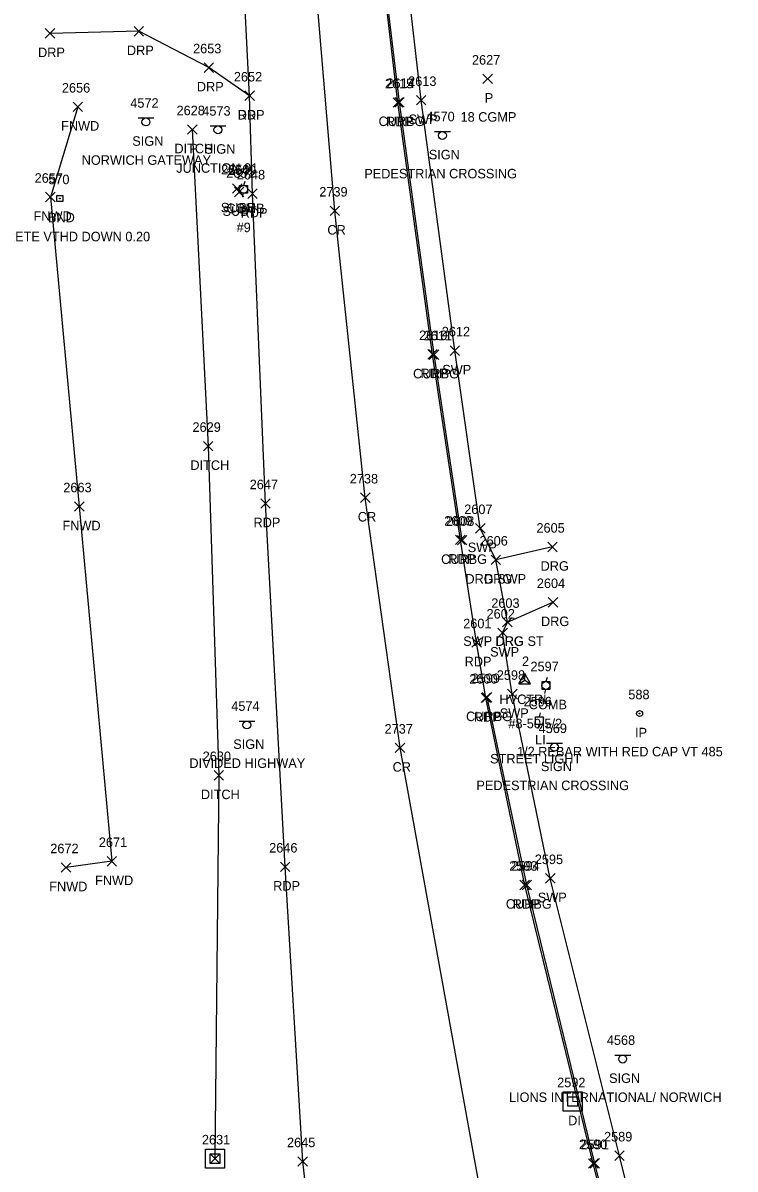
# Model space of a CAD drawing. Extents: x 1690689 to 1696275, y 438760 to 444007.
# Drawn here: x 1691174.2 to 1691323.9, y 441126.4 to 441367.3 of the extents above; entities that cross this region are included whole.
import ezdxf

# ---------------------------------------------------------------- set-up
doc = ezdxf.new("R2010")
doc.units = 0
for name, color, linetype in [('C_A', 7, 'Continuous'), ('C_I', 7, 'Continuous'), ('CPSM', 7, 'Continuous'), ('D_A', 7, 'Continuous'), ('D_C', 7, 'Continuous'), ('D_I', 7, 'Continuous'), ('D_TIC', 7, 'Continuous'), ('DD', 7, 'Continuous'), ('DS', 7, 'Continuous'), ('L_A', 7, 'Continuous'), ('L_I', 7, 'Continuous'), ('L_TIC', 7, 'Continuous'), ('Level 18', 7, 'Continuous'), ('LFNC', 7, 'Continuous'), ('M_A', 7, 'Continuous'), ('M_C', 7, 'Continuous'), ('M_I', 7, 'Continuous'), ('MPIR', 7, 'Continuous'), ('P_A', 7, 'Continuous'), ('P_I', 7, 'Continuous'), ('P_TIC', 7, 'Continuous'), ('PET', 7, 'Continuous'), ('PRC', 7, 'Continuous'), ('R_A', 7, 'Continuous'), ('R_I', 7, 'Continuous'), ('R_TIC', 7, 'Continuous'), ('RC', 7, 'Continuous'), ('RDG', 7, 'Continuous'), ('RDP', 7, 'Continuous'), ('RSW', 7, 'Continuous'), ('S_A', 7, 'Continuous'), ('S_C', 7, 'Continuous'), ('S_I', 7, 'Continuous'), ('SSGN', 7, 'Continuous'), ('U_A', 7, 'Continuous'), ('U_C', 7, 'Continuous'), ('U_I', 7, 'Continuous'), ('U_TIC', 7, 'Continuous'), ('ULP', 7, 'Continuous'), ('UP', 7, 'Continuous')]:
    doc.layers.add(name, color=color, linetype=linetype)

msp = doc.modelspace()

# ---------------------------------------------------------------- linework, layer by layer
at = {"layer": 'CPSM'}
for p, q in [((1691278.46, 441228.43), (1691279.71, 441230.59)), ((1691280.96, 441228.43), (1691279.71, 441230.59)), ((1691279.71, 441229.15), (1691279.71, 441230.59)), ((1691278.46, 441228.43), (1691279.71, 441229.15)), ((1691278.46, 441228.43), (1691280.96, 441228.43)), ((1691279.71, 441229.15), (1691279.71, 441229.15)), ((1691279.71, 441229.15), (1691280.96, 441228.43))]:
    msp.add_line(p, q, dxfattribs=at)
at = {"layer": 'D_TIC'}
for points in [[(1691270.93, 441354.56), (1691272.93, 441356.56)], [(1691272.93, 441354.56), (1691270.93, 441356.56)], [(1691208.82, 441343.92), (1691210.82, 441345.92)], [(1691210.82, 441343.92), (1691208.82, 441345.92)], [(1691208.82, 441343.92), (1691210.82, 441345.92)], [(1691210.82, 441343.92), (1691208.82, 441345.92)], [(1691212.17, 441277.37), (1691214.17, 441279.37)], [(1691214.17, 441277.37), (1691212.17, 441279.37)], [(1691214.39, 441208.17), (1691216.39, 441210.17)], [(1691216.39, 441208.17), (1691214.39, 441210.17)], [(1691213.58, 441127.6), (1691215.58, 441129.6)], [(1691215.58, 441127.6), (1691213.58, 441129.6)]]:
    msp.add_lwpolyline(points, dxfattribs=at)
at = {"layer": 'DD'}
msp.add_lwpolyline([(1691209.82, 441344.92), (1691213.17, 441278.37), (1691215.39, 441209.17), (1691214.58, 441128.6)], dxfattribs=at)
at = {"layer": 'DS'}
for p, q in [((1691287.79, 441142.62), (1691291.79, 441142.62)), ((1691287.79, 441138.62), (1691287.79, 441142.62)), ((1691291.79, 441142.62), (1691291.79, 441138.62)), ((1691288.79, 441139.62), (1691288.79, 441141.62)), ((1691288.79, 441141.62), (1691290.79, 441141.62)), ((1691289.79, 441140.62), (1691289.79, 441140.62)), ((1691289.79, 441140.62), (1691289.79, 441140.62)), ((1691290.79, 441141.62), (1691290.79, 441139.62)), ((1691291.79, 441138.62), (1691287.79, 441138.62)), ((1691290.79, 441139.62), (1691288.79, 441139.62)), ((1691212.58, 441130.6), (1691216.58, 441130.6)), ((1691212.58, 441126.6), (1691212.58, 441130.6)), ((1691216.58, 441130.6), (1691216.58, 441126.6)), ((1691213.58, 441127.6), (1691213.58, 441129.6)), ((1691213.58, 441129.6), (1691215.58, 441129.6)), ((1691214.58, 441128.6), (1691214.58, 441128.6)), ((1691214.58, 441128.6), (1691214.58, 441128.6)), ((1691215.58, 441129.6), (1691215.58, 441127.6)), ((1691216.58, 441126.6), (1691212.58, 441126.6)), ((1691215.58, 441127.6), (1691213.58, 441127.6))]:
    msp.add_line(p, q, dxfattribs=at)
at = {"layer": 'L_TIC'}
for points in [[(1691184.76, 441348.68), (1691186.76, 441350.68)], [(1691186.76, 441348.68), (1691184.76, 441350.68)], [(1691178.97, 441329.72), (1691180.97, 441331.72)], [(1691180.97, 441329.72), (1691178.97, 441331.72)], [(1691185.05, 441264.67), (1691187.05, 441266.67)], [(1691187.05, 441264.67), (1691185.05, 441266.67)], [(1691182.27, 441188.81), (1691184.27, 441190.81)], [(1691184.27, 441188.81), (1691182.27, 441190.81)], [(1691191.91, 441190.11), (1691193.91, 441192.11)], [(1691193.91, 441190.11), (1691191.91, 441192.11)]]:
    msp.add_lwpolyline(points, dxfattribs=at)
at = {"layer": 'Level 18'}
msp.add_lwpolyline([(1691181.35, 441331.04), (1691182.6, 441331.04), (1691182.6, 441329.79), (1691181.35, 441329.79)], close=True, dxfattribs=at)
msp.add_circle((1691181.98, 441330.42), 0.0833, dxfattribs=at)
at = {"layer": 'LFNC'}
msp.add_lwpolyline([(1691185.76, 441349.68), (1691179.97, 441330.72), (1691186.05, 441265.67), (1691192.91, 441191.11), (1691183.27, 441189.81)], dxfattribs=at)
at = {"layer": 'MPIR'}
for radius in [0.625, 0.0833]:
    msp.add_circle((1691303.87, 441222.16), radius, dxfattribs=at)
at = {"layer": 'P_TIC'}
for points in [[(1691220.87, 441351.01), (1691222.87, 441353.01)], [(1691222.87, 441351.01), (1691220.87, 441353.01)], [(1691252.06, 441349.59), (1691254.06, 441351.59)], [(1691254.06, 441349.59), (1691252.06, 441351.59)], [(1691221.49, 441330.42), (1691223.49, 441332.42)], [(1691223.49, 441330.42), (1691221.49, 441332.42)], [(1691238.79, 441326.83), (1691240.79, 441328.83)], [(1691240.79, 441326.83), (1691238.79, 441328.83)], [(1691259.33, 441296.66), (1691261.33, 441298.66)], [(1691261.33, 441296.66), (1691259.33, 441298.66)], [(1691245.19, 441266.52), (1691247.19, 441268.52)], [(1691247.19, 441266.52), (1691245.19, 441268.52)], [(1691224.2, 441265.32), (1691226.2, 441267.32)], [(1691226.2, 441265.32), (1691224.2, 441267.32)], [(1691265.18, 441257.66), (1691267.18, 441259.66)], [(1691267.18, 441257.66), (1691265.18, 441259.66)], [(1691268.6, 441236.09), (1691270.6, 441238.09)], [(1691270.6, 441236.09), (1691268.6, 441238.09)], [(1691270.54, 441224.45), (1691272.54, 441226.45)], [(1691272.54, 441224.45), (1691270.54, 441226.45)], [(1691252.5, 441213.94), (1691254.5, 441215.94)], [(1691254.5, 441213.94), (1691252.5, 441215.94)], [(1691228.34, 441188.95), (1691230.34, 441190.95)], [(1691230.34, 441188.95), (1691228.34, 441190.95)], [(1691278.71, 441185.12), (1691280.71, 441187.12)], [(1691280.71, 441185.12), (1691278.71, 441187.12)], [(1691232.04, 441127.02), (1691234.04, 441129.02)], [(1691234.04, 441127.02), (1691232.04, 441129.02)], [(1691293.14, 441126.58), (1691295.14, 441128.58)], [(1691295.14, 441126.58), (1691293.14, 441128.58)]]:
    msp.add_lwpolyline(points, dxfattribs=at)
at = {"layer": 'PET'}
for points in [[(1691238.51, 441080.26), (1691233.04, 441128.02), (1691229.34, 441189.95), (1691225.2, 441266.32), (1691222.49, 441331.42), (1691221.87, 441352.01), (1691219.29, 441402.36), (1691215.78, 441404.57), (1691214.66, 441461.76), (1691212.86, 441499.57), (1691209.68, 441553.6), (1691203.53, 441618.53), (1691198.8, 441650.27), (1691198.82, 441652.13), (1691193.05, 441693.14)], [(1691309.01, 441068.57), (1691294.14, 441127.58), (1691279.71, 441186.12), (1691271.54, 441225.45), (1691269.6, 441237.09), (1691266.18, 441258.66), (1691260.33, 441297.66), (1691253.06, 441350.59), (1691250.02, 441376.37), (1691249.19, 441394.8), (1691248.99, 441398.05), (1691250.15, 441432.81), (1691248.61, 441468.02), (1691245.58, 441519.21), (1691242.31, 441569.35), (1691239.58, 441608.7), (1691238.35, 441622.76), (1691233.07, 441677.78)]]:
    msp.add_lwpolyline(points, dxfattribs=at)
at = {"layer": 'PRC'}
msp.add_lwpolyline([(1691277.81, 441080.96), (1691253.5, 441214.94), (1691246.19, 441267.52), (1691239.79, 441327.83), (1691235.79, 441375.29), (1691233.27, 441422.2), (1691229.73, 441505.18), (1691226.6, 441557.92), (1691222.02, 441618.83), (1691218.57, 441657.04), (1691144.02, 442182.42), (1691112.43, 442376.83), (1691097.75, 442454.48), (1691089.73, 442499.13), (1691078.44, 442565.84)], dxfattribs=at)
at = {"layer": 'R_TIC'}
for points in [[(1691197.59, 441364.55), (1691199.59, 441366.55)], [(1691199.59, 441364.55), (1691197.59, 441366.55)], [(1691178.9, 441364.12), (1691180.9, 441366.12)], [(1691180.9, 441364.12), (1691178.9, 441366.12)], [(1691212.28, 441356.93), (1691214.28, 441358.93)], [(1691214.28, 441356.93), (1691212.28, 441358.93)], [(1691220.87, 441351.01), (1691222.87, 441353.01)], [(1691222.87, 441351.01), (1691220.87, 441353.01)], [(1691256.94, 441350.07), (1691258.94, 441352.07)], [(1691258.94, 441350.07), (1691256.94, 441352.07)], [(1691252.39, 441349.64), (1691254.39, 441351.64)], [(1691254.39, 441349.64), (1691252.39, 441351.64)], [(1691264.01, 441297.44), (1691266.01, 441299.44)], [(1691266.01, 441297.44), (1691264.01, 441299.44)], [(1691259.65, 441296.6), (1691261.65, 441298.6)], [(1691261.65, 441296.6), (1691259.65, 441298.6)], [(1691269.38, 441260.09), (1691271.38, 441262.09)], [(1691271.38, 441260.09), (1691269.38, 441262.09)], [(1691265.55, 441257.61), (1691267.55, 441259.61)], [(1691267.55, 441257.61), (1691265.55, 441259.61)], [(1691284.56, 441256.18), (1691286.56, 441258.18)], [(1691286.56, 441256.18), (1691284.56, 441258.18)], [(1691272.65, 441253.47), (1691274.65, 441255.47)], [(1691274.65, 441253.47), (1691272.65, 441255.47)], [(1691272.65, 441253.47), (1691274.65, 441255.47)], [(1691274.65, 441253.47), (1691272.65, 441255.47)], [(1691284.65, 441244.54), (1691286.65, 441246.54)], [(1691286.65, 441244.54), (1691284.65, 441246.54)], [(1691275.06, 441240.38), (1691277.06, 441242.38)], [(1691277.06, 441240.38), (1691275.06, 441242.38)], [(1691275.06, 441240.38), (1691277.06, 441242.38)], [(1691277.06, 441240.38), (1691275.06, 441242.38)], [(1691274.07, 441238.13), (1691276.07, 441240.13)], [(1691276.07, 441238.13), (1691274.07, 441240.13)], [(1691276.1, 441225.25), (1691278.1, 441227.25)], [(1691278.1, 441225.25), (1691276.1, 441227.25)], [(1691270.8, 441224.57), (1691272.8, 441226.57)], [(1691272.8, 441224.57), (1691270.8, 441226.57)], [(1691284.09, 441186.52), (1691286.09, 441188.52)], [(1691286.09, 441186.52), (1691284.09, 441188.52)], [(1691279.16, 441185.14), (1691281.16, 441187.14)], [(1691281.16, 441185.14), (1691279.16, 441187.14)], [(1691293.46, 441126.62), (1691295.46, 441128.62)], [(1691295.46, 441126.62), (1691293.46, 441128.62)], [(1691298.65, 441128.23), (1691300.65, 441130.23)], [(1691300.65, 441128.23), (1691298.65, 441130.23)]]:
    msp.add_lwpolyline(points, dxfattribs=at)
at = {"layer": 'RC'}
for points in [[(1691266.55, 441258.61), (1691260.65, 441297.6), (1691253.39, 441350.64), (1691250.33, 441376.39), (1691249.86, 441386.32), (1691249.36, 441394.53)], [(1691450.76, 440430.58), (1691444.92, 440435.07), (1691439.78, 440439.75), (1691432.93, 440448.9), (1691426.12, 440467.24), (1691417.19, 440505.54), (1691412.4, 440527.61), (1691405.01, 440565.67), (1691398.01, 440602.6), (1691382.66, 440685.49), (1691370.67, 440750.86), (1691351.95, 440846.96), (1691330.25, 440958.42), (1691317.04, 441030.78), (1691309.36, 441068.61), (1691294.46, 441127.62), (1691280.16, 441186.14), (1691271.8, 441225.57)]]:
    msp.add_lwpolyline(points, dxfattribs=at)
at = {"layer": 'RDG'}
for points in [[(1691285.56, 441257.18), (1691273.65, 441254.47)], [(1691276.06, 441241.38), (1691285.65, 441245.54)]]:
    msp.add_lwpolyline(points, dxfattribs=at)
at = {"layer": 'RDP'}
msp.add_lwpolyline([(1691221.87, 441352.01), (1691213.28, 441357.93), (1691198.59, 441365.55), (1691179.9, 441365.12)], dxfattribs=at)
at = {"layer": 'RSW'}
msp.add_lwpolyline([(1691314.28, 441069.9), (1691299.65, 441129.23), (1691285.09, 441187.52), (1691277.1, 441226.25), (1691275.07, 441239.13), (1691276.06, 441241.38), (1691273.65, 441254.47), (1691270.38, 441261.09), (1691265.01, 441298.44), (1691257.94, 441351.07), (1691254.91, 441377.51), (1691253.99, 441386.62), (1691249.86, 441386.32)], dxfattribs=at)
at = {"layer": 'SSGN'}
for p, q in [((1691198.41, 441347.34), (1691201.75, 441347.34)), ((1691200.06, 441346.51), (1691200.06, 441346.51)), ((1691213.55, 441345.67), (1691216.89, 441345.67)), ((1691215.2, 441344.84), (1691215.2, 441344.84)), ((1691260.75, 441344.5), (1691264.09, 441344.5)), ((1691262.4, 441343.66), (1691262.4, 441343.66)), ((1691219.64, 441220.59), (1691222.97, 441220.59)), ((1691221.29, 441219.75), (1691221.29, 441219.75)), ((1691284.32, 441215.91), (1691287.66, 441215.91)), ((1691285.97, 441215.08), (1691285.97, 441215.08)), ((1691298.66, 441150.37), (1691302, 441150.37)), ((1691300.31, 441149.54), (1691300.31, 441149.54))]:
    msp.add_line(p, q, dxfattribs=at)
for centre in [(1691200.06, 441346.51), (1691215.2, 441344.84), (1691262.4, 441343.66), (1691221.29, 441219.75), (1691285.97, 441215.08), (1691300.31, 441149.54)]:
    msp.add_circle(centre, 0.833, dxfattribs=at)
at = {"layer": 'U_TIC'}
for points in [[(1691218.27, 441331.5), (1691220.27, 441333.5)], [(1691220.27, 441331.5), (1691218.27, 441333.5)], [(1691218.68, 441330.77), (1691220.68, 441332.77)], [(1691220.68, 441330.77), (1691218.68, 441332.77)]]:
    msp.add_lwpolyline(points, dxfattribs=at)
at = {"layer": 'ULP'}
for p, q in [((1691282.95, 441222.34), (1691282.78, 441221.5)), ((1691281.95, 441219.84), (1691281.95, 441221.5)), ((1691281.95, 441221.5), (1691283.62, 441221.5)), ((1691283.62, 441219.84), (1691281.95, 441219.84)), ((1691282.53, 441219), (1691282.78, 441219.84)), ((1691282.78, 441220.67), (1691282.78, 441220.67)), ((1691283.62, 441221.5), (1691283.62, 441219.84))]:
    msp.add_line(p, q, dxfattribs=at)
at = {"layer": 'UP'}
for p, q in [((1691219.77, 441331.5), (1691219.77, 441333.17)), ((1691219.77, 441333.17), (1691221.44, 441333.17)), ((1691220.86, 441334), (1691220.61, 441333.17)), ((1691221.44, 441333.17), (1691221.44, 441331.5)), ((1691221.44, 441331.5), (1691219.77, 441331.5)), ((1691220.36, 441330.67), (1691220.61, 441331.5)), ((1691220.61, 441332.34), (1691220.61, 441332.34)), ((1691284.43, 441229.73), (1691284.18, 441228.9)), ((1691283.35, 441227.23), (1691283.35, 441228.9)), ((1691283.35, 441228.9), (1691285.02, 441228.9)), ((1691285.02, 441227.23), (1691283.35, 441227.23)), ((1691283.93, 441226.4), (1691284.18, 441227.23)), ((1691284.18, 441228.06), (1691284.18, 441228.06)), ((1691285.02, 441228.9), (1691285.02, 441227.23))]:
    msp.add_line(p, q, dxfattribs=at)
for centre in [(1691220.61, 441332.34), (1691284.18, 441228.06)]:
    msp.add_circle(centre, 0.833, dxfattribs=at)

# ---------------------------------------------------------------- texts
at = {"layer": 'C_A'}
msp.add_text('HVCTRL', height=2, dxfattribs=at).set_placement((1691274.4, 441224.15))
at = {"layer": 'C_I'}
msp.add_text('2', height=2, dxfattribs=at).set_placement((1691279.14, 441232.15))
at = {"layer": 'D_A'}
for s, p in [('P', (1691271.31, 441350.56)), ('DITCH', (1691206.06, 441339.92)), ('P', (1691209.2, 441339.92)), ('DITCH', (1691209.41, 441273.37)), ('DITCH', (1691211.63, 441204.17)), ('DI', (1691288.85, 441135.62))]:
    msp.add_text(s, height=2, dxfattribs=at).set_placement(p)
at = {"layer": 'D_C'}
msp.add_text('18 CGMP', height=2, dxfattribs=at).set_placement((1691266.22, 441346.56))
at = {"layer": 'D_I'}
for s, p in [('2627', (1691268.62, 441358.56)), ('2628', (1691206.51, 441347.92)), ('2628', (1691206.51, 441347.92)), ('2629', (1691209.86, 441281.37)), ('2630', (1691212, 441212.17)), ('2592', (1691286.53, 441143.62)), ('2631', (1691211.84, 441131.6)), ('2631', (1691211.84, 441131.6))]:
    msp.add_text(s, height=2, dxfattribs=at).set_placement(p)
at = {"layer": 'L_A'}
for p in [(1691182.23, 441344.68), (1691176.44, 441325.72), (1691182.52, 441260.67), (1691179.74, 441184.81), (1691189.38, 441186.11)]:
    msp.add_text('FNWD', height=2, dxfattribs=at).set_placement(p)
at = {"layer": 'L_I'}
for s, p in [('2656', (1691182.4, 441352.68)), ('2657', (1691176.67, 441333.72)), ('2663', (1691182.7, 441268.67)), ('2671', (1691190.17, 441194.11)), ('2672', (1691179.96, 441192.81))]:
    msp.add_text(s, height=2, dxfattribs=at).set_placement(p)
at = {"layer": 'M_A'}
for s, p in [('BND', (1691179.47, 441325.42)), ('IP', (1691302.91, 441217.16))]:
    msp.add_text(s, height=2, dxfattribs=at).set_placement(p)
at = {"layer": 'M_C'}
for s, p in [('4X4 CONCRETE VTHD DOWN 0.20', (1691157.26, 441321.42)), ('1/2 REBAR WITH RED CAP VT 485', (1691278.1, 441213.16))]:
    msp.add_text(s, height=2, dxfattribs=at).set_placement(p)
at = {"layer": 'M_I'}
for s, p in [('570', (1691179.53, 441333.42)), ('588', (1691301.5, 441225.16))]:
    msp.add_text(s, height=2, dxfattribs=at).set_placement(p)
at = {"layer": 'P_A'}
for s, p in [('RDP', (1691219.36, 441347.01)), ('RDP', (1691250.55, 441345.59)), ('RDP', (1691219.98, 441326.42)), ('CR', (1691238.22, 441322.83)), ('RDP', (1691257.82, 441292.66)), ('RDP', (1691222.69, 441261.32)), ('CR', (1691244.62, 441262.52)), ('RDP', (1691263.67, 441253.66)), ('RDP', (1691267.08, 441232.09)), ('RDP', (1691269.03, 441220.45)), ('CR', (1691251.93, 441209.94)), ('RDP', (1691226.83, 441184.95)), ('RDP', (1691277.19, 441181.12))]:
    msp.add_text(s, height=2, dxfattribs=at).set_placement(p)
at = {"layer": 'P_I'}
for s, p in [('2652', (1691218.56, 441355.01)), ('2615', (1691250.32, 441353.59)), ('2648', (1691219.18, 441334.42)), ('2739', (1691236.52, 441330.83)), ('2610', (1691257.5, 441300.66)), ('2647', (1691221.89, 441269.32)), ('2738', (1691242.93, 441270.52)), ('2609', (1691262.79, 441261.66)), ('2601', (1691266.78, 441240.09)), ('2600', (1691268.07, 441228.45)), ('2737', (1691250.24, 441217.94)), ('2646', (1691225.98, 441192.95)), ('2593', (1691276.45, 441189.12)), ('2645', (1691229.73, 441131.02)), ('2591', (1691291.45, 441130.58))]:
    msp.add_text(s, height=2, dxfattribs=at).set_placement(p)
at = {"layer": 'R_A'}
for s, p in [('DRP', (1691177.39, 441360.12)), ('DRP', (1691196.07, 441360.55)), ('DRP', (1691210.77, 441352.93)), ('DRP', (1691219.36, 441347.01)), ('CURBG', (1691248.98, 441345.64)), ('SWP', (1691255.3, 441346.07)), ('CURBG', (1691256.24, 441292.6)), ('SWP', (1691262.38, 441293.44)), ('SWP', (1691267.74, 441256.09)), ('CURBG', (1691262.13, 441253.61)), ('DRG', (1691283.05, 441252.18)), ('DRG SWP', (1691267.24, 441249.47)), ('DRG', (1691271.14, 441249.47)), ('DRG', (1691283.13, 441240.54)), ('SWP DRG ST', (1691266.78, 441236.38)), ('DRG', (1691273.55, 441236.38)), ('SWP', (1691272.44, 441234.13)), ('CURBG', (1691267.38, 441220.57)), ('SWP', (1691274.46, 441221.25)), ('SWP', (1691282.46, 441182.52)), ('CURBG', (1691275.74, 441181.14))]:
    msp.add_text(s, height=2, dxfattribs=at).set_placement(p)
at = {"layer": 'R_I'}
for s, p in [('2653', (1691209.98, 441360.93)), ('2652', (1691218.56, 441355.01)), ('2614', (1691250.65, 441353.64)), ('2613', (1691255.2, 441354.07)), ('2611', (1691258.48, 441300.6)), ('2612', (1691262.27, 441301.44)), ('2607', (1691266.99, 441264.09)), ('2608', (1691263.16, 441261.61)), ('2605', (1691282.18, 441260.18)), ('2606', (1691270.21, 441257.47)), ('2606', (1691270.21, 441257.47)), ('2604', (1691282.26, 441248.54)), ('2603', (1691272.68, 441244.38)), ('2603', (1691272.68, 441244.38)), ('2602', (1691271.69, 441242.13)), ('2599', (1691268.53, 441228.57)), ('2598', (1691273.84, 441229.25)), ('2594', (1691276.9, 441189.14)), ('2595', (1691281.83, 441190.52)), ('2589', (1691296.39, 441132.23)), ('2590', (1691291.12, 441130.62))]:
    msp.add_text(s, height=2, dxfattribs=at).set_placement(p)
at = {"layer": 'S_A'}
for p in [(1691197.2, 441341.49), (1691212.34, 441339.82), (1691259.54, 441338.64), (1691218.42, 441214.73), (1691283.11, 441210.06), (1691297.45, 441144.52)]:
    msp.add_text('SIGN', height=2, dxfattribs=at).set_placement(p)
at = {"layer": 'S_C'}
for s, p in [('NORWICH GATEWAY', (1691186.56, 441337.49)), ('JUNCTION 91', (1691206.44, 441335.82)), ('PEDESTRIAN CROSSING', (1691245.98, 441334.64)), ('DIVIDED HIGHWAY', (1691209.2, 441210.73)), ('PEDESTRIAN CROSSING', (1691269.55, 441206.06)), ('LIONS INTERNATIONAL/ NORWICH', (1691276.4, 441140.52))]:
    msp.add_text(s, height=2, dxfattribs=at).set_placement(p)
at = {"layer": 'S_I'}
for s, p in [('4572', (1691196.78, 441349.49)), ('4573', (1691211.92, 441347.82)), ('4570', (1691259.04, 441346.64)), ('4574', (1691218.01, 441222.73)), ('4569', (1691282.64, 441218.06)), ('4568', (1691296.98, 441152.52))]:
    msp.add_text(s, height=2, dxfattribs=at).set_placement(p)
at = {"layer": 'U_A'}
for s, p in [('SUBE', (1691215.81, 441327.5)), ('SUBT', (1691216.18, 441326.77)), ('COMB', (1691216.99, 441327.34)), ('COMB', (1691280.57, 441223.06)), ('LI', (1691281.89, 441215.67))]:
    msp.add_text(s, height=2, dxfattribs=at).set_placement(p)
at = {"layer": 'U_C'}
for s, p in [('#9', (1691219.14, 441323.34)), ('#8-50/5/2', (1691276.28, 441219.06)), ('STREET LIGHT', (1691272.44, 441211.67))]:
    msp.add_text(s, height=2, dxfattribs=at).set_placement(p)
at = {"layer": 'U_I'}
for s, p in [('2650', (1691215.88, 441335.5)), ('2651', (1691216.94, 441334.77)), ('2649', (1691217.29, 441335.34)), ('2597', (1691280.92, 441231.06)), ('2596', (1691279.47, 441223.67))]:
    msp.add_text(s, height=2, dxfattribs=at).set_placement(p)

doc.saveas('drawing.dxf')
